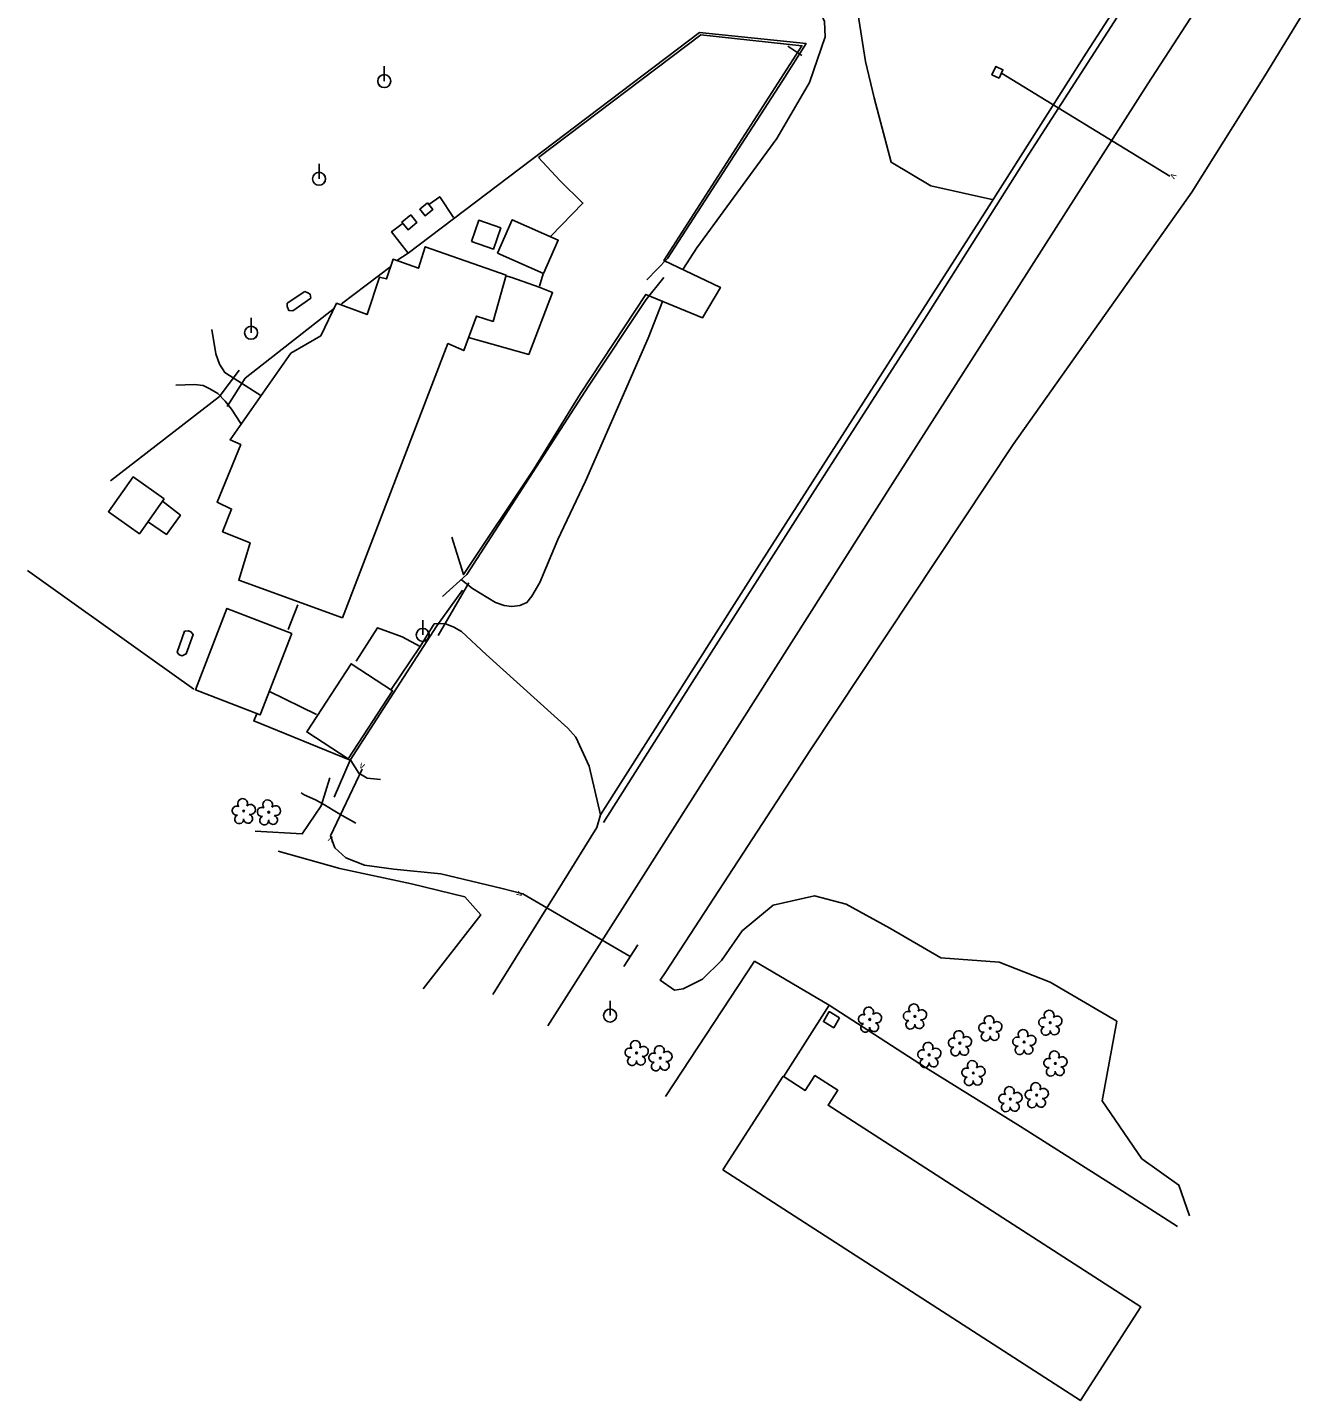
# Model space of a CAD drawing. Extents: x 1840200 to 1849051, y 348278 to 353012.
# Drawn here: x 1843778 to 1844264, y 349461 to 349980 of the extents above; entities that cross this region are included whole.
import ezdxf

# ---------------------------------------------------------------- set-up
doc = ezdxf.new("R2010")
doc.units = 0
for name, color, linetype in [('Default', 7, 'Continuous'), ('Exist Building', 7, 'Continuous'), ('Exist Building Deck Patio', 7, 'Continuous'), ('Exist Building Paved Walk Topo', 7, 'Continuous'), ('Exist Hydro Stream or Body of Water', 7, 'Continuous'), ('Exist Other Culture Fence Line', 7, 'Continuous'), ('Exist Roads Change in Surface', 7, 'Continuous'), ('Exist Roads EOP', 7, 'Continuous'), ('Exist Roads EOP Other', 7, 'Continuous'), ('Exist Roads EOT', 7, 'Continuous'), ('Exist Roads Soil', 7, 'Continuous'), ('Exist Structure Minor Culvert Topo', 7, 'Continuous'), ('Exist Structure Minor Head and End Wall', 7, 'Continuous'), ('Exist Utilities Other Pole CELL', 7, 'Continuous'), ('Exist Utilities Power Pole CELL', 7, 'Continuous'), ('Exist Vegetation Tree CELL', 7, 'Continuous'), ('Exist Vegetation Woods Line', 7, 'Continuous'), ('Old_Level_6', 7, 'Continuous'), ('Old_Level_8', 7, 'Continuous')]:
    doc.layers.add(name, color=color, linetype=linetype)

# ---------------------------------------------------------------- blocks, each defined once
blk = doc.blocks.new('EXIST UTILITIES OTHER POLE')
at = {"layer": 'Exist Utilities Other Pole CELL'}
blk.add_circle((0, 0), 0.0493, dxfattribs=at)
blk = doc.blocks.new('EXIST VEGETATION TREE')
at = {"layer": 'Exist Vegetation Tree CELL'}
blk.add_line((0, 0), (0, 0), dxfattribs=at)
blk.add_circle((0, 0), 0.00652, dxfattribs=at)
for centre, radius, start, end in [((-0.052, 0.003), 0.0345, 62.6636, 279.3457), ((-0.008, 0.057), 0.0371, 330.1651, 219.7134), ((0.051, 0.012), 0.038, 257.1011, 134.1999), ((-0.034, -0.062), 0.0338, 111.5671, 6.231), ((0.033, -0.058), 0.034, 181.2822, 74.56)]:
    blk.add_arc(centre, radius, start, end, dxfattribs=at)
blk = doc.blocks.new('EXIST UTILITIES POWER POLE')
at = {"layer": 'Exist Utilities Power Pole CELL'}
for q in [(0, 0.1125), (0, 0)]:
    blk.add_line((0, 0), q, dxfattribs=at)
blk.add_circle((0, 0), 0.049, dxfattribs=at)

msp = doc.modelspace()

# ---------------------------------------------------------------- linework, layer by layer
at = {"layer": 'Exist Building'}
for points in [[(1843928.89, 349914.01), (1843930.86, 349911.53), (1843927.91, 349909.18), (1843925.94, 349911.66)], [(1843922.54, 349909.47), (1843924.85, 349906.62), (1843921.48, 349903.9), (1843919.17, 349906.75)], [(1843945.46, 349899.39), (1843953.83, 349896.55), (1843956.56, 349904.6), (1843948.2, 349907.45)], [(1843955.27, 349895.03), (1843972.69, 349887.31), (1843978.3, 349899.93), (1843960.89, 349907.65)], [(1843896.76, 349757.07), (1843936.56, 349860.84), (1843942.58, 349858.16), (1843947.39, 349871.2), (1843953.63, 349869.2), (1843958.55, 349886.74), (1843927.99, 349897.46), (1843925.45, 349889.29), (1843915.85, 349892.71), (1843913.39, 349885.27), (1843910.65, 349885.96), (1843905.98, 349871.77), (1843894.46, 349876.11), (1843888.58, 349863.77), (1843877.17, 349857.16), (1843854.2, 349824.43), (1843858.24, 349822.64), (1843849.31, 349800.79), (1843854.78, 349798.25), (1843851.35, 349789.64), (1843861.77, 349785.41), (1843857.48, 349771.41)], [(1843829.26, 349802.09), (1843819.94, 349788.92), (1843808.23, 349797.2), (1843817.54, 349810.37)], [(1843877.54, 349751.12), (1843865.59, 349720.37), (1843841.07, 349729.9), (1843853.02, 349760.65)], [(1843898.85, 349703.74), (1843915.63, 349729.55), (1843899.95, 349739.77), (1843883.17, 349713.96)], [(1844040.51, 349548.3), (1844175.72, 349461.09), (1844198.55, 349496.48), (1844080.31, 349572.75), (1844083.96, 349578.41), (1844075.3, 349583.98), (1844071.69, 349578.38), (1844063.36, 349583.74)]]:
    msp.add_lwpolyline(points, close=True, dxfattribs=at)
at = {"layer": 'Exist Building Deck Patio'}
msp.add_lwpolyline([(1843822.95, 349793.51), (1843830.18, 349788.64), (1843835.4, 349795.89), (1843828.64, 349801.23)], dxfattribs=at)
at = {"layer": 'Exist Building Paved Walk Topo'}
for p, q in [((1844065.11, 349973.33), (1844070.42, 349969.72)), ((1844019.59, 349892.97), (1844011.81, 349884.94)), ((1844011.48, 349877.5), (1844018.15, 349885.85)), ((1843850.17, 349840.75), (1843857.66, 349850.72)), ((1843859.91, 349847.75), (1843853.12, 349837.07)), ((1843943.73, 349773.51), (1843934.52, 349765.16)), ((1843932.37, 349754.13), (1843942.06, 349767.6)), ((1843838.44, 349752.2), (1843836.99, 349752)), ((1843899.6, 349703.32), (1843893.55, 349689.29)), ((1843888.66, 349685.96), (1843891.96, 349696.65))]:
    msp.add_line(p, q, dxfattribs=at)
for points in [[(1843882.49, 349880.46), (1843875.83, 349876.06), (1843875.74, 349874.84), (1843876.39, 349873.39), (1843877.97, 349873.19), (1843884.75, 349877.97)], [(1843884.75, 349877.97), (1843884.44, 349879.54), (1843883.58, 349880.06), (1843882.49, 349880.46)], [(1843836.99, 349752), (1843834.25, 349744.13), (1843834.78, 349743.3), (1843835.34, 349742.96), (1843836.1, 349742.69), (1843837.62, 349743.43), (1843840.29, 349750.75), (1843839.38, 349751.83), (1843838.44, 349752.2), (1843837.51, 349752.04)]]:
    msp.add_lwpolyline(points, dxfattribs=at)
at = {"layer": 'Exist Hydro Stream or Body of Water'}
msp.add_lwpolyline([(1843964.84, 349652.68), (1843957.1, 349654.69), (1843933.87, 349660.29), (1843916.18, 349662.02), (1843905.05, 349663.62), (1843897.96, 349666.37), (1843893.83, 349670.11), (1843892.23, 349674.63)], dxfattribs=at)
at = {"layer": 'Exist Other Culture Fence Line'}
for p, q in [((1843921.58, 349895.08), (1843917.2, 349892.24)), ((1843915.01, 349889.99), (1843896.3, 349875.82)), ((1843893.74, 349874.18), (1843859.91, 349847.75)), ((1843850.17, 349840.75), (1843808.97, 349808.96)), ((1843899.6, 349703.32), (1843932.37, 349754.13)), ((1844063.5, 349583.47), (1844080.71, 349610.62))]:
    msp.add_line(p, q, dxfattribs=at)
for points in [[(1844019.59, 349892.97), (1844063.06, 349960.22), (1844072.01, 349974.28), (1844031.66, 349978.52), (1843921.58, 349895.08), (1843915.27, 349903.15), (1843919.28, 349906.06)], [(1843929.39, 349913.39), (1843933.45, 349916.33), (1843938.67, 349908.55)], [(1843943.73, 349773.51), (1843989.69, 349844.77), (1844011.48, 349877.5)], [(1843840.47, 349730.1), (1843823.87, 349742.01), (1843777.6, 349774.96)], [(1843899.6, 349703.32), (1843863.13, 349718.13), (1843864.3, 349720.77)], [(1843888.66, 349685.96), (1843881.51, 349675.36), (1843863.67, 349676.45)], [(1844018.84, 349576.04), (1844052.49, 349627.22), (1844080.71, 349610.62), (1844117.09, 349587), (1844153.08, 349564.77), (1844191.56, 349540.29), (1844212.36, 349526.86)]]:
    msp.add_lwpolyline(points, dxfattribs=at)
at = {"layer": 'Exist Roads Change in Surface'}
for points in [[(1843971.08, 349882.18), (1843960.74, 349885.87), (1843958.41, 349886.44)], [(1843944.29, 349863.18), (1843967.13, 349856.7), (1843976.13, 349880.1), (1843971.08, 349882.18)]]:
    msp.add_lwpolyline(points, dxfattribs=at)
at = {"layer": 'Exist Roads EOP'}
for points in [[(1843953.54, 349614.62), (1843979.84, 349656.88), (1843992.92, 349677.81), (1843994.32, 349682.6), (1844055.09, 349778.44), (1844139.39, 349910.12), (1844177.9, 349970.62), (1844224.49, 350042.87), (1844225.38, 350046.89), (1844226.7, 350052.39)], [(1844249.35, 350033.32), (1844201.2, 349959.08), (1844152.57, 349882.73), (1844105.59, 349809.27), (1844059.62, 349737.01), (1844009.61, 349658.33), (1843974.36, 349602.86)]]:
    msp.add_lwpolyline(points, dxfattribs=at)
at = {"layer": 'Exist Roads EOP Other'}
for p, q in [((1844032.17, 349977.64), (1843970.76, 349931.2)), ((1843971.2, 349882.56), (1843972.57, 349887.24)), ((1843876.12, 349752.74), (1843879.86, 349762.08)), ((1843926.06, 349746.29), (1843914.85, 349729.58)), ((1843868.81, 349729.39), (1843886.92, 349720.54))]:
    msp.add_line(p, q, dxfattribs=at)
for points in [[(1844032.17, 349977.64), (1844070.38, 349973.48), (1844018.23, 349892.22), (1844039.58, 349882.04), (1844032.88, 349870.59), (1844011.46, 349879.39), (1843986.72, 349841.96)], [(1843970.76, 349931.2), (1843978.86, 349922.56), (1843987.64, 349913.95), (1843975.53, 349901.44)], [(1843986.72, 349841.96), (1843969.01, 349813.39), (1843942.48, 349773.43), (1843938.01, 349787.6)], [(1843901.86, 349740.77), (1843909.9, 349753.27), (1843919.32, 349749.9), (1843926.06, 349746.29)]]:
    msp.add_lwpolyline(points, dxfattribs=at)
at = {"layer": 'Exist Roads EOT'}
msp.add_lwpolyline([(1843995.34, 349679.65), (1844028.05, 349731.26), (1844074.33, 349803.82), (1844117.6, 349871.45), (1844156.2, 349932.5), (1844198.3, 349997.92), (1844226.68, 350041.93), (1844228.78, 350046.47), (1844229.93, 350049.83)], dxfattribs=at)
at = {"layer": 'Exist Roads Soil'}
for points in [[(1844065.63, 350093.91), (1844059.24, 350080.41), (1844056.84, 350073.01), (1844062.16, 350051.78), (1844071.47, 350032.41), (1844091.61, 349985.9), (1844094.41, 349967.53), (1844097.71, 349953.77), (1844104.12, 349929.43), (1844119.1, 349920.54), (1844142.85, 349915.25)], [(1843954.12, 350026.55), (1843976.98, 350024.23), (1843995.37, 350022.57), (1844010.8, 350019.39), (1844025.93, 350014.64), (1844047.97, 350007.91), (1844060.58, 350003.3), (1844072.64, 349993.27), (1844076.38, 349988.25), (1844077.92, 349984.93), (1844078.99, 349982.66), (1844079.23, 349976.79), (1844073.31, 349959.6), (1844060.9, 349938.33), (1844030.63, 349897.06), (1844025.36, 349888.87)], [(1843941.69, 349771.49), (1843945.82, 349768.14), (1843954.51, 349762.96), (1843957.88, 349761.77), (1843960.69, 349761.44), (1843963.79, 349761.73), (1843966.44, 349762.86), (1843968.34, 349765.32), (1843971.29, 349770.48), (1843978.08, 349786.76), (1843988.54, 349808.83), (1844012.33, 349862.91), (1844017.76, 349876.68)], [(1843865.78, 349841.15), (1843857.15, 349846.72), (1843852.27, 349849.84), (1843850.26, 349853.07), (1843848.82, 349856.91), (1843847.34, 349866.19)], [(1843833.66, 349845.13), (1843840.7, 349845.36), (1843844, 349844.97), (1843846.6, 349843.74), (1843849.58, 349841.9), (1843852.34, 349839.04), (1843854.74, 349835.99), (1843858.22, 349830.54)], [(1843994.32, 349682.6), (1843989.97, 349700.96), (1843984.95, 349711.94), (1843981.9, 349715.33), (1843951.02, 349743.25), (1843941.71, 349751.94), (1843938.82, 349753.57), (1843935.44, 349754.92), (1843931.38, 349754.82), (1843926.06, 349746.29)], [(1843899.89, 349703.17), (1843902.9, 349698.33), (1843906.05, 349696.45), (1843911.07, 349695.93)], [(1843901.73, 349679.39), (1843896.64, 349682.33), (1843895.07, 349683.26), (1843893.2, 349684.38), (1843889.86, 349686.33), (1843886.45, 349688.29), (1843882.16, 349690.21), (1843881.06, 349690.87)]]:
    msp.add_lwpolyline(points, dxfattribs=at)
at = {"layer": 'Exist Structure Minor Culvert Topo'}
for points in [[(1844145.86, 349963.12), (1844209.57, 349924.17)], [(1843932.85, 349750.42), (1843944.48, 349770.3)], [(1843904.18, 349699.9), (1843892.23, 349674.63)], [(1844005.51, 349629.06), (1843964.84, 349652.68)]]:
    msp.add_lwpolyline(points, dxfattribs=at)
at = {"layer": 'Exist Structure Minor Head and End Wall'}
msp.add_line((1844008.39, 349633.46), (1844003.12, 349625.26), dxfattribs=at)
at = {"layer": 'Exist Vegetation Woods Line'}
for points in [[(1844019.02, 349623.22), (1844073.69, 349707.12), (1844150.32, 349822.65), (1844217.8, 349918.12), (1844245.45, 349962.07), (1844278.2, 350015.83), (1844293.1, 350029.39)], [(1843872.38, 349668.87), (1843895.67, 349662.35), (1843922.79, 349656.51), (1843942.93, 349651.6), (1843949.06, 349644.74), (1843927.2, 349616.84)], [(1844216.93, 349530.95), (1844212.86, 349542.59), (1844198.99, 349552.49), (1844183.88, 349574.4), (1844189.51, 349604.51), (1844164.29, 349619.32), (1844144.93, 349626.91), (1844122.98, 349628.47), (1844103.7, 349639.68), (1844087.11, 349648.79), (1844075.11, 349651.93), (1844059.48, 349648.38), (1844047.77, 349638.69), (1844040.04, 349627.53), (1844032.79, 349620.39), (1844025.56, 349616.81), (1844022.21, 349616.33)], [(1844022.21, 349616.33), (1844016.86, 349620.03), (1844019.02, 349623.22)]]:
    msp.add_lwpolyline(points, dxfattribs=at)
at = {"layer": 'Old_Level_6'}
msp.add_lwpolyline([(1844144.94, 349961.22), (1844146.41, 349964.37), (1844143.74, 349965.62), (1844142.26, 349962.47)], close=True, dxfattribs=at)
at = {"layer": 'Old_Level_8'}
msp.add_lwpolyline([(1844084.68, 349605.88), (1844082.44, 349602.1), (1844078.53, 349604.43), (1844080.77, 349608.21)], close=True, dxfattribs=at)

# ---------------------------------------------------------------- block references
at = {"layer": 'Default', "xscale": 50, "yscale": 50}
for name, p in [('EXIST UTILITIES OTHER POLE', (1843912.5, 349960.09)), ('EXIST UTILITIES OTHER POLE', (1843887.83, 349923.14)), ('EXIST UTILITIES OTHER POLE', (1843862.14, 349864.91)), ('EXIST UTILITIES OTHER POLE', (1843927.03, 349750.65)), ('EXIST VEGETATION TREE', (1843859.35, 349684.03)), ('EXIST VEGETATION TREE', (1843868.82, 349683.57)), ('EXIST UTILITIES OTHER POLE', (1843997.87, 349606.67)), ('EXIST VEGETATION TREE', (1844096.07, 349605.19)), ('EXIST VEGETATION TREE', (1844113.12, 349606.36)), ('EXIST VEGETATION TREE', (1844164.3, 349604)), ('EXIST VEGETATION TREE', (1844141.6, 349601.9)), ('EXIST VEGETATION TREE', (1844130.11, 349596.24)), ('EXIST VEGETATION TREE', (1844154.44, 349596.69)), ('EXIST VEGETATION TREE', (1844007.88, 349592.55)), ('EXIST VEGETATION TREE', (1844016.87, 349590.6)), ('EXIST VEGETATION TREE', (1844118.52, 349591.84)), ('EXIST VEGETATION TREE', (1844166.22, 349588.59)), ('EXIST VEGETATION TREE', (1844135.23, 349584.98)), ('EXIST VEGETATION TREE', (1844149.23, 349575.1)), ('EXIST VEGETATION TREE', (1844159.16, 349576.61))]:
    msp.add_blockref(name, p, dxfattribs=at)
at = {"layer": 'Exist Utilities Power Pole CELL', "xscale": 50, "yscale": 50}
for p in [(1843912.5, 349960.09), (1843887.83, 349923.14), (1843862.14, 349864.91), (1843927.03, 349750.65), (1843997.87, 349606.67)]:
    msp.add_blockref('EXIST UTILITIES POWER POLE', p, dxfattribs=at)

# ---------------------------------------------------------------- texts
at = {"layer": 'Exist Structure Minor Culvert Topo'}
for rotation, p in [(238.8003, (1844210.35, 349925.46)), (334.4582, (1843902.82, 349700.55)), (154.9399, (1843893.59, 349674)), (60.0973, (1843964.09, 349651.38))]:
    msp.add_text('v', height=2.65, rotation=rotation, dxfattribs=at).set_placement(p)

doc.saveas('drawing.dxf')
